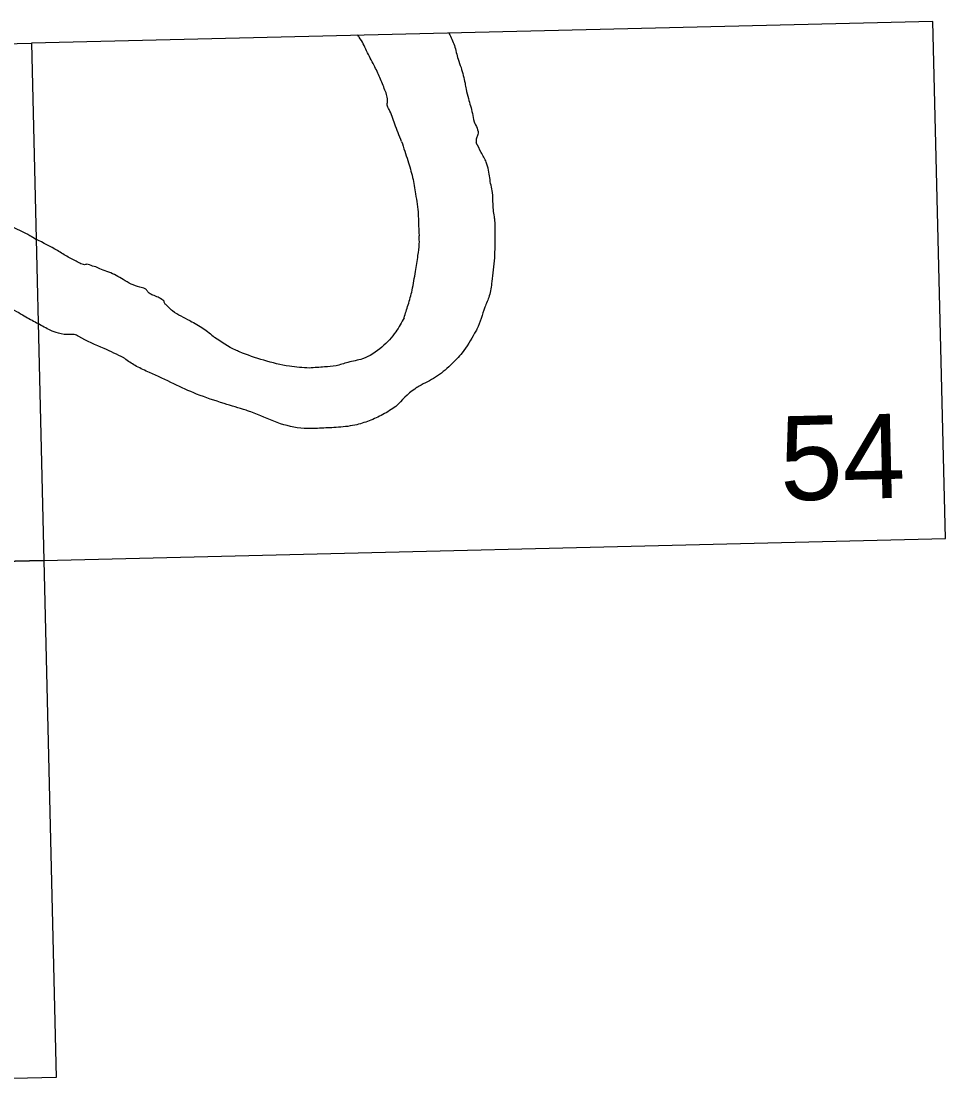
# Model space of a CAD drawing. Extents: x 3683613 to 3738215, y 469626 to 495384.
# Drawn here: x 3710217 to 3711500, y 472869 to 474365 of the extents above; entities that cross this region are included whole.
import ezdxf

# ---------------------------------------------------------------- set-up
doc = ezdxf.new("R2010")
doc.units = 0
doc.layers.add('V-ANNO-NPLT', color=7, linetype='Continuous')

msp = doc.modelspace()

# ---------------------------------------------------------------- linework, layer by layer
at = {"layer": 'V-ANNO-NPLT'}
for points in [[(3711482.1, 474364.8), (3710231.1, 474334.6), (3710248.1, 473616.6)], [(3710248.1, 473616.6), (3711499.8, 473646.8), (3711482.1, 474364.8)], [(3708996.3, 473587.5), (3708979.9, 474305.4), (3710231.1, 474334.6), (3710248.1, 473616.6)], [(3710248.1, 473616.6), (3708996.3, 473587.5)], [(3709012.7, 472869.5), (3708996.3, 473587.5), (3710248.1, 473616.6), (3710265.1, 472898.6)], [(3710265.1, 472898.6), (3709012.7, 472869.5)]]:
    msp.add_lwpolyline(points, dxfattribs=at)
for points in [[(3710744.9, 474198.2), (3710735.4, 474222.4), (3710727.4, 474242.8), (3710724.9, 474248.6), (3710725.3, 474253.5), (3710721.7, 474269.5), (3710714.7, 474286.9), (3710706.7, 474303.8), (3710696.3, 474324.1), (3710685.9, 474343), (3710683.2, 474346.1)], [(3710810.5, 474348.6), (3710818.2, 474331.4), (3710823.3, 474312.5), (3710827.3, 474300.8), (3710832.9, 474279), (3710834.4, 474270.8), (3710837.5, 474257.7), (3710843.1, 474237.3), (3710845.7, 474225.7), (3710850.7, 474207.7), (3710848.8, 474202.8), (3710848.4, 474196.5)], [(3710744.9, 474198.2), (3710753.5, 474171.6), (3710760.1, 474148.3), (3710764.2, 474125.5), (3710768, 474096.8), (3710768.1, 474085.6), (3710769.3, 474067.2)], [(3710874, 474091.2), (3710871.8, 474111.2), (3710871.1, 474127.2), (3710869, 474137.4), (3710865.4, 474158.3), (3710862.4, 474169.4), (3710855.4, 474183), (3710848.4, 474196.5)], [(3710171.3, 474096.7), (3710197.4, 474083), (3710205.5, 474079.1), (3710228.6, 474067.9), (3710237.2, 474062.5)], [(3710874, 474091.2), (3710874.2, 474068.4), (3710873.6, 474036.8), (3710870.1, 474003.6), (3710866.5, 473983.7), (3710860.3, 473968), (3710849.5, 473937.7), (3710846.2, 473931.9)], [(3710748.2, 473953.6), (3710753.9, 473971.2), (3710759.5, 473991.7), (3710764, 474017.5), (3710767.6, 474039.9), (3710769.4, 474056), (3710769.3, 474067.2)], [(3710296.5, 474030), (3710282.2, 474037.7), (3710267.1, 474046.7), (3710237.2, 474062.5)], [(3710451.4, 473949.2), (3710426.9, 473963), (3710422, 473967.3), (3710418.6, 473971.1), (3710415.6, 473974), (3710415.1, 473976.5), (3710413.6, 473977.9), (3710399.5, 473985), (3710394.6, 473987.4), (3710392.1, 473990.3), (3710388.7, 473993.7), (3710381.4, 473996), (3710358.4, 474006.4), (3710338.4, 474016.9), (3710328.1, 474020.7), (3710320.3, 474024), (3710311.5, 474026.8), (3710308.1, 474027.7), (3710306.2, 474027.2), (3710303.2, 474027.2), (3710296.4, 474030)], [(3710176.1, 473981.7), (3710188.2, 473974.3), (3710213.4, 473960.6), (3710223.4, 473954.7), (3710240.3, 473945.3)], [(3710451.4, 473949.2), (3710469.5, 473938.7), (3710485.2, 473926.2)], [(3710748.2, 473953.6), (3710736.8, 473934), (3710717.6, 473912.8), (3710690.6, 473896.5), (3710670.2, 473891.4), (3710653.8, 473886.8), (3710637.8, 473885.2), (3710616.9, 473883.5)], [(3710359.2, 473898), (3710331.8, 473910.8), (3710296.6, 473927.4), (3710290.3, 473930.3), (3710284.9, 473930.2), (3710268.4, 473931.9), (3710257.2, 473936.2), (3710240.3, 473945.3)], [(3710846.2, 473931.9), (3710829, 473904.9), (3710812.7, 473887.7), (3710792, 473870.9), (3710769.3, 473858.5), (3710763, 473854.5), (3710737, 473830.4)], [(3710616.9, 473883.5), (3710589.2, 473886.1), (3710553.6, 473894.4), (3710519.9, 473906.2), (3710514.5, 473908.5), (3710485.2, 473926.2)], [(3710529.1, 473825), (3710498.4, 473834.4), (3710460.3, 473847.6), (3710428.6, 473861.8), (3710394.9, 473877.5), (3710376.8, 473886), (3710362.1, 473895.6), (3710359.2, 473898)], [(3710737, 473830.4), (3710718.7, 473819), (3710699.9, 473810.5), (3710680, 473804.4), (3710653.8, 473801.2), (3710631, 473800), (3710609.6, 473799.7), (3710572.1, 473808), (3710535.5, 473822.7), (3710529.1, 473825)]]:
    msp.add_spline(points, degree=3, dxfattribs=at)

# ---------------------------------------------------------------- texts
msp.add_text('54', height=117, rotation=1.3827, dxfattribs=at).set_placement((3711271.1, 473699.5))

doc.saveas('drawing.dxf')
